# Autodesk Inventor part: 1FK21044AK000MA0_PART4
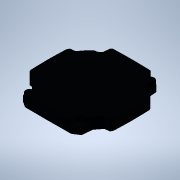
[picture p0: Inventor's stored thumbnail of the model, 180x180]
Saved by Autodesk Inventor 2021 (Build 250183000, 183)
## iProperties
Created: 2025-04
Part Number: 1FK21044AK000MA0_PART4
Material: Generic
Catalog Web Link: www.3dfindit.com
Description: -Servo synchronous motor
Document SubType Name: Modeling
Designer: psAdmin
Mass: 55.5405 g
Surface Area: 149.572 cm^2
Volume: 55.5405 cm^3
Density: 1 g/cm^3
Appearance: PSOLRGB-38-46-56
Category: PARTsolutions
Title: 1FK21044AK000MA0_PART4
Author: Cadenas PARTsolutions
Comments: Servo synchronous motor
Sending System: PARTsolutions
Preprocessor: ST-DEVELOPER v19.3
PSOL_IDENT_0: {$CADENAS_DATA/23d-libs/siemens_ag/_cat_/87/f4/1fk21044ak000ma0.prj},213 {VTYP=3D},{NB=1FK21044AK000
PSOL_IDENT_1: MA0_PART4},{LINA=1FK21044AK000MA0_PART4},{NN=1FK21044AK000MA0_PART4},{NOPRJ=TRUE},{DATE=19.08.2025 1
PSOL_IDENT_2: 4:00:48},{GEOMDATE=30.07.2025 02:00:50},{VERSION=},{LINEID=10},{WBVAR=},{WBNUMERIC=}  {NB=1FK21044AK
PSOL_IDENT_3: 000MA0_PART4},{LINA=1FK21044AK000MA0_PART4},{KT=DUMMY},{PREVIEW=../../../_pool_/cb/72/p_d211_xx_0043
PSOL_IDENT_4: 4j.png},{DESCSHORT=SIMOTICS S-1FK2 HD, SINAMICS S210 3AC 400V-480V, 0.95 Nm, 6000 rpm},{DESCLONG=SIM
PSOL_IDENT_5: OTICS S-1FK2 HD servo motor M0=1.27 Nm; PN = 0.6 kW at nN=6000 rpm (380-480 V); PN = 0.4 kW at nN=30
PSOL_IDENT_6: 00 rpm (200-240 V); degree of protection IP64; cylindrical shaft D19x40mm; absolute encoder 22-bit +
PSOL_IDENT_7: 12-bit multiturn (encoder AM22DQC); with OCC interface; plug size M17, rotatable; SIMOTICS S-1FK2 s
PSOL_IDENT_8: ervomotorfor a wide range of uses in industrial environments. SIMOTICS S‑1FK2 servomotors are compac
PSOL_IDENT_9: t synchronous motors with a high dynamic performance that set themselves apart as a result of their
PSOL_IDENT_10: high power density, degree of protection and overload capability. The motors are available in two va
PSOL_IDENT_11: riants: as High Dynamic variant (highest dynamic performance as a result of the low intrinsic moment
PSOL_IDENT_12: of inertia for applications demanding a high dynamic performance with low moved masses) - and as Co
PSOL_IDENT_13: mpact variant (precise and stable closed-loop control for medium up to large moved masses as a resul
PSOL_IDENT_14: t of a medium intrinsic moment of inertia). SIMOTICSS‑1FK2 servomotors fully exploit their strengths
PSOL_IDENT_15: in a system with the SINAMICSS210 frequency converter and simple connection using the one cable con
PSOL_IDENT_16: nection (OCC). Advantages include the short control and positioning times, fast and precise correcti
PSOL_IDENT_17: on of disturbing quantities as well as stable control with a high dynamic performance. The servo mot
PSOL_IDENT_18: ors can be configured to address a wide range of requirements. For example with and without holding
PSOL_IDENT_19: brake, IP64 or IP65 degree of protection, singleturn or multiturn absolute encoders - to name just a
PSOL_IDENT_20: few. Further, the servomotors are available in different shaft heights extending from 20 to 100. A
PSOL_IDENT_21: shaft sealing ring is available to achieve an IP65 degree of protection and for subsequent mounting
PSOL_IDENT_22: at the motor or as spare part. SIMOTICS - the optimum motor for each and every motion control applic
PSOL_IDENT_23: ation.},{INTNO=195125056312},{SUPPLIERALTNO=1FK2104-4AK00-0MA0},{MANUID=1FK21044AK000MA0},{MANUNAME=
PSOL_IDENT_24: Siemens},{MANUTYPEDESC=Synchronous motor 1FK2-HD 1,27 Nm},{AAU732=SIMOTICS},{AAO057=S-1FK2},{AAU734=
PSOL_IDENT_25: SIMOTICS S-1FK2 HD servo motor M0=1.27 Nm; PN = 0.6 kW at nN=6000 rpm (380-480 V); PN = 0.4 kW at nN=
PSOL_IDENT_26: 3000 rpm (200-240 V); degree of protection IP64; cylindrical shaft D19x40mm; absolute encoder 22-bit
PSOL_IDENT_27: + 12-bit multiturn (encoder AM22DQC); with OCC interface; plug size M17, rotatable;},{AAW338=Synchr
PSOL_IDENT_28: onous motor 1FK2-HD 1,27 Nm},{AAO742=SIMOTICS},{AAO663=4042948690994},{NOCUPEROU=1},{PRICEQUANTITY=1
PSOL_IDENT_29: },{QUANTITYMIN=1},{QUANTITYINT=1},{CTN=85015100},{COO=DE},{AAO676=1FK2104-4AK00-0MA0},{AAO677=Siemen
PSOL_IDENT_30: s AG},{ORDERUNIT=C62},{CONTENTUNIT=C62}
NB: 1FK21044AK000MA0_PART4
NT: Servo synchronous motor
NBSYN: $MANUID._PART4
LINA: 1FK21044AK000MA0_PART4
CATALOG: SIEMENS
PREVIEW: ../../../_pool_/cb/72/p_d211_xx_00434j.png
DESCSHORT: SIMOTICS S-1FK2 HD, SINAMICS S210 3AC 400V-480V, 0.95 Nm, 6000 rpm
DESCLONG: SIMOTICS S-1FK2 HD servo motor M0=1.27 Nm; PN = 0.6 kW at nN=6000 rpm (380-480 V); PN = 0.4 kW at nN=3000 rpm (200-240 V); degree of protection IP64; cylindrica
INTNO: 195125056312
SUPPLIERALTNO: 1FK2104-4AK00-0MA0
MANUID: 1FK21044AK000MA0
MANUNAME: Siemens
MANUTYPEDESC: Synchronous motor 1FK2-HD 1,27 Nm
AAU732: SIMOTICS
AAO057: S-1FK2
AAU734: SIMOTICS S-1FK2 HD servo motor M0=1.27 Nm; PN = 0.6 kW at nN=6000 rpm (380-480 V); PN = 0.4 kW at nN=3000 rpm (200-240 V); degree of protection IP64; cylindrica
AAW338: Synchronous motor 1FK2-HD 1,27 Nm
AAO742: SIMOTICS
AAO663: 4042948690994.0
NOCUPEROU: 1
PRICEQUANTITY: 1
QUANTITYMIN: 1
QUANTITYINT: 1
CTN: 85015100
COO: DE
ARTICLENO: 1FK21044AK000MA0_PART4
BOMINFO: 1FK21044AK000MA0_PART4
CREATOR: CADENAS GmbH
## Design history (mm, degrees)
feature "2025_04_17_15_37_40_0494"
body "Solid1"
